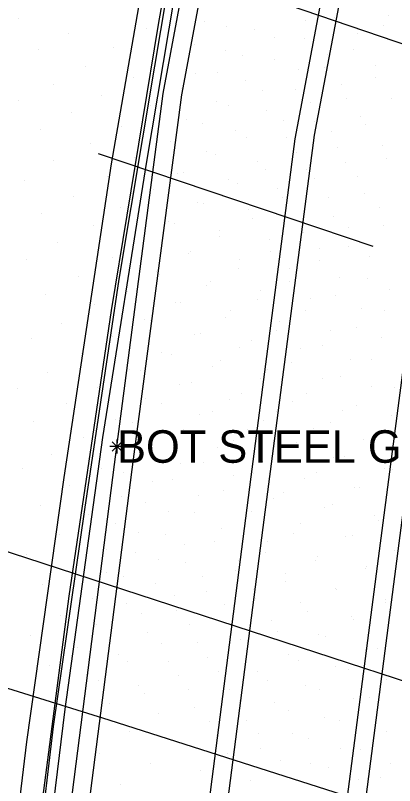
# Model space of a CAD drawing. Extents: x 1733582 to 1734070, y 467256 to 468256.
# Drawn here: x 1733820.12 to 1733841.15, y 467694.29 to 467736.94 of the extents above; entities that cross this region are included whole.
import ezdxf

# ---------------------------------------------------------------- set-up
doc = ezdxf.new("R2010")
doc.units = 0
for name, color, linetype in [('Default', 7, 'Continuous'), ('S_Bridge_Curb', 7, 'Continuous'), ('S_Bridge_Deck', 7, 'Continuous'), ('S_Bridge_Rail', 7, 'Continuous'), ('S_Ground_SpotElevation', 7, 'Continuous'), ('S_Misc_MiscFeature', 7, 'Continuous'), ('S_Misc_MiscItems', 7, 'Continuous'), ('S_Roadway_Edge_Pavement', 7, 'Continuous'), ('S_Roadway_Painted_Lines', 7, 'Continuous'), ('S_Text', 7, 'Continuous')]:
    doc.layers.add(name, color=color, linetype=linetype)

# ---------------------------------------------------------------- blocks, each defined once
blk = doc.blocks.new('POINT_DISPLAY')
at = {"layer": 'Default'}
blk.add_line((0, 0), (0, 0), dxfattribs=at)

msp = doc.modelspace()

# ---------------------------------------------------------------- linework, layer by layer
at = {"layer": 'S_Bridge_Curb'}
msp.add_lwpolyline([(1733818.159, 467663.732), (1733819.385, 467674.582), (1733820.64, 467684.116), (1733822.243, 467697.564), (1733823.972, 467709.579), (1733825.87, 467722.342), (1733827.859, 467734.138), (1733830.216, 467748.192), (1733832.11, 467758.256), (1733834.51, 467770.45), (1733837.898, 467787.063), (1733840.865, 467800.549), (1733844.359, 467815.787), (1733847.831, 467829.289), (1733850.56, 467839.861), (1733853.05, 467849.061), (1733854.563, 467854.584)], dxfattribs=at)
at = {"layer": 'S_Bridge_Deck'}
msp.add_lwpolyline([(1733855.138, 467854.785), (1733853.086, 467847.693), (1733849.22, 467833.073), (1733845.482, 467818.291), (1733842.048, 467803.532), (1733838.704, 467788.663), (1733835.558, 467773.547), (1733832.728, 467759.072), (1733829.896, 467743.681), (1733827.379, 467728.743), (1733824.957, 467713.563), (1733822.869, 467698.529), (1733821.029, 467683.583), (1733819.201, 467668.729), (1733818.621, 467663.409)], dxfattribs=at)
at = {"layer": 'S_Bridge_Rail'}
msp.add_lwpolyline([(1733818.359, 467665.855), (1733819.171, 467673.048), (1733821.039, 467688.917), (1733823.113, 467704.785), (1733825.46, 467720.602), (1733828.058, 467736.434), (1733830.845, 467752.168), (1733833.805, 467767.85), (1733837.016, 467783.594), (1733840.405, 467799.172), (1733844.065, 467814.724), (1733847.908, 467830.326), (1733851.933, 467845.769), (1733853.853, 467852.641)], dxfattribs=at)
at = {"layer": 'S_Misc_MiscFeature'}
for points in [[(1733819.146, 467662.128), (1733822.411, 467687.138), (1733825.625, 467712.064), (1733828.308, 467732.621), (1733831.184, 467747.947), (1733833.505, 467760.094), (1733835.806, 467771.99), (1733838.257, 467784.633), (1733839.477, 467789.916), (1733843.642, 467806.605), (1733849.69, 467830.62), (1733855.796, 467855.018)], [(1733820.122, 467661.91), (1733823.472, 467687.541), (1733826.672, 467712.367), (1733829.355, 467732.542), (1733832.44, 467748.988), (1733834.659, 467760.701), (1733836.916, 467772.404), (1733839.778, 467786.991), (1733844.946, 467807.685), (1733851.172, 467832.455), (1733856.733, 467854.727)], [(1733826.53, 467660.119), (1733830.278, 467688.775), (1733833.202, 467711.396), (1733835.635, 467730.109), (1733838.854, 467747.125), (1733841.053, 467758.65), (1733843.35, 467770.62), (1733845.821, 467783.336), (1733847.212, 467789.204), (1733851.47, 467806.186), (1733857.516, 467830.268), (1733863.15, 467852.64)], [(1733852.432, 467852.088), (1733847.956, 467835.582), (1733844.668, 467822.664), (1733840.962, 467807.205), (1733837.376, 467791.545), (1733834.11, 467775.918), (1733831.093, 467760.248), (1733828.17, 467744.438), (1733825.424, 467728.718), (1733822.802, 467711.353), (1733820.741, 467696.705), (1733817.897, 467673.275), (1733817.169, 467667.027)], [(1733864.079, 467852.275), (1733858.131, 467828.607), (1733852.049, 467804.339), (1733847.192, 467785.066), (1733844.207, 467769.696), (1733841.988, 467758.102), (1733839.394, 467744.549), (1733836.696, 467730.312), (1733833.835, 467708.583), (1733831.31, 467688.992), (1733827.509, 467659.844)], [(1733833.862, 467657.682), (1733837.178, 467683.156), (1733840.254, 467706.86), (1733843.003, 467727.895), (1733846.149, 467744.535), (1733848.346, 467756.071), (1733850.647, 467768.07), (1733853.573, 467783.047), (1733858.608, 467802.95), (1733864.671, 467827.038), (1733870.472, 467850.181)], [(1733871.393, 467849.822), (1733865.695, 467826.963), (1733859.504, 467802.42), (1733854.508, 467782.647), (1733851.621, 467767.768), (1733849.286, 467755.703), (1733847.085, 467744.185), (1733843.99, 467727.733), (1733841.143, 467705.862), (1733838.187, 467683.149), (1733834.828, 467657.424)]]:
    msp.add_lwpolyline(points, dxfattribs=at)
at = {"layer": 'S_Misc_MiscItems'}
for p, q in [((1733826.018, 467712.806), (1733825.494, 467713.33)), ((1733826.018, 467713.33), (1733825.494, 467712.806)), ((1733825.756, 467713.461), (1733825.756, 467712.675)), ((1733826.149, 467713.068), (1733825.363, 467713.068))]:
    msp.add_line(p, q, dxfattribs=at)
at = {"layer": 'S_Roadway_Edge_Pavement'}
msp.add_lwpolyline([(1733586.071, 467770.749), (1733667.71, 467746.624), (1733748.731, 467721.817), (1733825.312, 467697.928), (1733923.075, 467666.68), (1733975.856, 467650.261), (1734036.534, 467629.484)], dxfattribs=at)
at = {"layer": 'S_Roadway_Painted_Lines'}
msp.add_line((1733824.711, 467729.301), (1733839.939, 467724.157), dxfattribs=at)
for points in [[(1733600.615, 467812.285), (1733624.074, 467805.253), (1733650.091, 467797.478), (1733690.162, 467785.254), (1733709.513, 467779.192), (1733740.833, 467769.059), (1733764.442, 467761.384), (1733801.856, 467748.917), (1733825.1, 467741.003), (1733865.745, 467727.157), (1733942.114, 467701.157), (1734018.088, 467674.904), (1734046.328, 467664.849)], [(1733588.359, 467777.226), (1733663.015, 467755.304), (1733706.127, 467742.598), (1733754.684, 467727.868), (1733796.902, 467714.64), (1733820.732, 467706.9), (1733859.007, 467694.431), (1733908.923, 467678.371), (1733969.097, 467659.316), (1734007.606, 467646.911), (1734038.438, 467636.916)]]:
    msp.add_lwpolyline(points, dxfattribs=at)

# ---------------------------------------------------------------- block references
at = {"layer": 'S_Ground_SpotElevation'}
for p in [(1733837.831, 467736.805), (1733840.795, 467736.912), (1733820.292, 467736.745), (1733830.629, 467736.597), (1733836.207, 467736.676), (1733840.516, 467736.391), (1733823.08, 467735.968), (1733827.367, 467736.227), (1733831.828, 467736.335), (1733833.401, 467736.159), (1733839.064, 467735.958), (1733834.475, 467735.728), (1733836.162, 467735.677), (1733825.543, 467735.183), (1733830.067, 467735.356), (1733821.387, 467735.04), (1733831.777, 467734.986), (1733832.718, 467734.746), (1733837.417, 467734.787), (1733838.897, 467735.044), (1733828.313, 467734.374), (1733834.492, 467734.524), (1733824.035, 467734.13), (1733831.328, 467733.801), (1733835.795, 467733.929), (1733837.248, 467734.06), (1733840.082, 467734.182), (1733826.681, 467733.514), (1733830.085, 467733.708), (1733840.098, 467733.515), (1733822.247, 467733.121), (1733832.889, 467733.347), (1733838.21, 467733.106), (1733829.335, 467732.913), (1733833.837, 467732.772), (1733835.658, 467732.835), (1733820.286, 467732.239), (1733824.88, 467732.487), (1733831.249, 467732.192), (1733836.463, 467732.141), (1733838.473, 467732.331), (1733840.977, 467732.32), (1733827.597, 467731.946), (1733831.935, 467731.953), (1733834.033, 467731.671), (1733823.218, 467731.579), (1733839.252, 467731.372), (1733829.582, 467731.205), (1733830.512, 467730.98), (1733834.98, 467731.118), (1733836.702, 467731.079), (1733839.534, 467730.895), (1733821.519, 467730.648), (1733825.978, 467730.78), (1733832.338, 467730.575), (1733837.637, 467730.522), (1733832.929, 467730.168), (1733835.17, 467730.184), (1733824.287, 467729.862), (1733828.705, 467729.943), (1733837.993, 467729.648), (1733840.456, 467729.756), (1733830.72, 467729.384), (1733831.227, 467729.222), (1733835.696, 467729.376), (1733822.231, 467728.897), (1733826.747, 467729.066), (1733833.532, 467728.865), (1733838.41, 467728.813), (1733840.674, 467729.045), (1733833.989, 467728.429), (1733836.27, 467728.396), (1733825.213, 467727.995), (1733829.094, 467728.21), (1733829.456, 467728.224), (1733831.921, 467727.853), (1733836.734, 467727.918), (1733839.083, 467728.035), (1733820.653, 467727.811), (1733832.43, 467727.62), (1733827.785, 467727.317), (1733834.679, 467727.368), (1733839.48, 467727.072), (1733823.34, 467726.929), (1733830.232, 467726.557), (1733834.919, 467726.881), (1733837.494, 467726.851), (1733825.969, 467726.304), (1733830.538, 467726.515), (1733833.043, 467726.2), (1733840.288, 467726.319), (1733821.565, 467725.966), (1733833.294, 467725.71), (1733837.769, 467725.834), (1733824.47, 467725.281), (1733828.632, 467725.528), (1733828.937, 467725.403), (1733835.827, 467725.542), (1733840.551, 467725.33), (1733831.423, 467725.033), (1733836.105, 467724.936), (1733838.617, 467725.225), (1733827.245, 467724.5), (1733831.443, 467724.681), (1733834.22, 467724.529), (1733822.434, 467724.358), (1733837.005, 467724.038), (1733838.586, 467724.156), (1733829.721, 467723.757), (1733829.857, 467723.867), (1733834.242, 467723.886), (1733839.747, 467723.568), (1733820.727, 467723.445), (1733825.487, 467723.537), (1733832.546, 467723.415), (1733836.988, 467723.347), (1733827.923, 467722.76), (1733832.508, 467722.944), (1733835.328, 467722.906), (1733823.627, 467722.481), (1733828.087, 467722.578), (1733838.082, 467722.442), (1733839.663, 467722.393), (1733830.709, 467721.96), (1733830.939, 467722.231), (1733835.34, 467722.194), (1733821.815, 467721.461), (1733826.36, 467721.668), (1733833.722, 467721.733), (1733837.846, 467721.451), (1733840.88, 467721.751), (1733829.005, 467721.052), (1733829.281, 467721.061), (1733833.557, 467721.204), (1733836.507, 467721.245), (1733824.528, 467720.938), (1733832.049, 467720.606), (1733836.226, 467720.617), (1733839.289, 467720.736), (1733840.602, 467720.615), (1733831.769, 467720.232), (1733822.662, 467719.871), (1733827.279, 467720.125), (1733827.615, 467720.06), (1733834.78, 467719.992), (1733830.405, 467719.346), (1733834.576, 467719.478), (1733837.591, 467719.495), (1733839.038, 467719.657), (1733821.041, 467719.034), (1733825.508, 467719.153), (1733830.029, 467719.28), (1733833.226, 467718.94), (1733840.432, 467719.09), (1733832.565, 467718.565), (1733835.958, 467718.509), (1733837.174, 467718.636), (1733823.798, 467718.232), (1733828.224, 467718.28), (1733828.753, 467718.182), (1733831.493, 467717.848), (1733835.423, 467717.717), (1733838.721, 467717.86), (1733839.861, 467717.905), (1733826.459, 467717.309), (1733827.079, 467717.278), (1733831.047, 467717.522), (1733834.123, 467717.338), (1733821.907, 467717.141), (1733833.723, 467716.844), (1733837.131, 467716.855), (1733838.129, 467716.937), (1733824.679, 467716.325), (1733829.221, 467716.509), (1733829.905, 467716.629), (1733839.891, 467716.37), (1733841.115, 467716.333), (1733820.237, 467716.278), (1733832.678, 467716.012), (1733836.288, 467715.99), (1733827.354, 467715.729), (1733828.236, 467715.471), (1733832.01, 467715.697), (1733835.462, 467715.557), (1733822.979, 467715.451), (1733838.271, 467715.054), (1733839.046, 467715.358), (1733830.344, 467714.819), (1733831.05, 467714.995), (1733834.584, 467714.991), (1733840.985, 467714.788), (1733821.138, 467714.438), (1733825.651, 467714.551), (1733826.635, 467714.421), (1733833.88, 467714.5), (1733837.607, 467714.403), (1733828.525, 467713.832), (1733829.42, 467713.993), (1733832.995, 467714.03), (1733836.657, 467714.059), (1733823.884, 467713.592), (1733832.234, 467713.427), (1733839.415, 467713.433), (1733840.158, 467713.572), (1733831.331, 467713.017), (1733834.847, 467713.021), (1733835.7, 467713.302), (1733822.12, 467712.638), (1733826.686, 467712.761), (1733827.72, 467712.677), (1733838.376, 467712.495), (1733829.3, 467712.137), (1733830.562, 467712.208), (1733833.845, 467712.25), (1733837.776, 467712.449), (1733820.516, 467711.834), (1733824.911, 467711.862), (1733836.824, 467711.656), (1733840.563, 467711.84), (1733841.037, 467711.816), (1733826.137, 467711.605), (1733828.852, 467711.235), (1733832.238, 467711.444), (1733833.331, 467711.596), (1733836.166, 467711.269), (1733823.143, 467710.906), (1733827.716, 467711.15), (1733838.929, 467710.81), (1733839.209, 467710.802), (1733831.66, 467710.622), (1733834.963, 467710.539), (1733826.006, 467710.31), (1733827.32, 467709.957), (1733830.279, 467710.333), (1733834.458, 467710.171), (1733821.54, 467709.804), (1733837.245, 467709.686), (1733837.681, 467709.832), (1733824.163, 467709.298), (1733828.605, 467709.474), (1733830.063, 467709.394), (1733833.236, 467709.485), (1733840.025, 467709.227), (1733825.652, 467708.796), (1733832.836, 467708.808), (1733835.913, 467708.823), (1733840.281, 467708.996), (1733826.931, 467708.314), (1733828.436, 467708.217), (1733831.578, 467708.539), (1733835.559, 467708.266), (1733822.567, 467708.195), (1733831.163, 467707.81), (1733834.075, 467707.813), (1733838.4, 467708.066), (1733838.817, 467708.114), (1733825.167, 467707.37), (1733829.516, 467707.619), (1733820.757, 467707.087), (1733826.787, 467707.195), (1733833.971, 467707.203), (1733836.851, 467706.975), (1733841.136, 467707.292), (1733828.037, 467706.821), (1733829.565, 467706.632), (1733832.489, 467706.778), (1733836.786, 467706.746), (1733823.342, 467706.375), (1733825.16, 467706.109), (1733832.319, 467706.198), (1733839.508, 467706.327), (1733839.578, 467706.421), (1733826.121, 467705.85), (1733830.498, 467705.856), (1733835.087, 467706.038), (1733821.631, 467705.448), (1733827.878, 467705.46), (1733835.122, 467705.59), (1733828.957, 467704.812), (1733830.716, 467705.028), (1733833.309, 467705.159), (1733837.85, 467705.208), (1733837.933, 467705.132), (1733824.385, 467704.631), (1733833.43, 467704.635), (1733835.924, 467704.417), (1733840.64, 467704.445), (1733840.656, 467704.572), (1733826.287, 467704.358), (1733829.08, 467703.984), (1733831.718, 467704.294), (1733836.294, 467703.947), (1733822.601, 467703.687), (1733827.126, 467703.809), (1733838.744, 467703.677), (1733824.621, 467703.185), (1733829.769, 467703.189), (1733831.851, 467703.262), (1733834.32, 467703.424), (1733838.894, 467703.487), (1733825.477, 467702.985), (1733827.456, 467702.744), (1733834.661, 467702.819), (1733820.969, 467702.616), (1733832.588, 467702.38), (1733836.919, 467702.661), (1733837.344, 467702.568), (1733823.54, 467701.921), (1733828.227, 467702.163), (1733830.213, 467702.204), (1733833.006, 467701.828), (1733839.645, 467701.823), (1733840.202, 467701.9), (1733825.827, 467701.557), (1733830.757, 467701.403), (1733835.291, 467701.525), (1733826.344, 467701.171), (1733828.587, 467701.171), (1733835.807, 467701.233), (1733821.989, 467700.917), (1733831.384, 467700.585), (1733833.538, 467700.6), (1733837.891, 467700.88), (1733838.598, 467700.734), (1733824.169, 467700.445), (1733824.74, 467700.123), (1733829.153, 467700.365), (1733840.712, 467700.138), (1733826.943, 467699.843), (1733834.102, 467700.097), (1733836.192, 467699.825), (1733827.279, 467699.398), (1733829.712, 467699.6), (1733831.97, 467699.593), (1733836.965, 467699.619), (1733832.54, 467698.983), (1733834.495, 467698.88), (1733838.884, 467699.106), (1733839.735, 467699.193), (1733825.317, 467698.81), (1733830.068, 467698.589), (1733835.273, 467698.462), (1733828.083, 467698.28), (1733837.24, 467698.06), (1733830.898, 467697.829), (1733832.913, 467697.87), (1733838.097, 467697.88), (1733826.427, 467697.271), (1733833.597, 467697.149), (1733835.476, 467697.176), (1733840.028, 467697.28), (1733840.683, 467697.296), (1733831.254, 467697.079), (1733836.372, 467696.892), (1733829.238, 467696.688), (1733833.74, 467696.322), (1733838.158, 467696.317), (1733839.24, 467696.315), (1733824.799, 467696.072), (1733831.895, 467696.047), (1733827.598, 467695.518), (1733834.797, 467695.695), (1733836.489, 467695.518), (1733840.93, 467695.514), (1733830.385, 467695.113), (1733837.504, 467695.313), (1733833.16, 467694.567), (1733839.162, 467694.638), (1733840.345, 467694.759), (1733825.953, 467694.353)]:
    msp.add_blockref('POINT_DISPLAY', p, dxfattribs=at)

# ---------------------------------------------------------------- texts
at = {"layer": 'S_Text'}
msp.add_text('BOT STEEL GIRDER', height=1.8, dxfattribs=at).set_placement((1733825.756, 467712.168))

doc.saveas('drawing.dxf')
